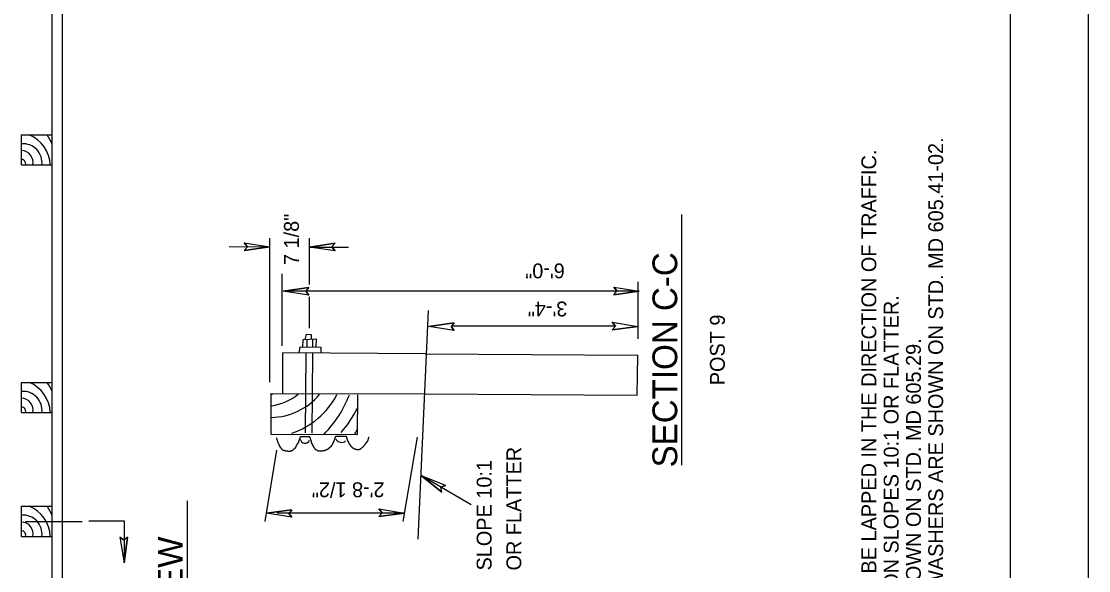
# Model space of a CAD drawing. Extents: x 12.2 to 54.5, y -7.8 to 16.1.
# Drawn here: x 50.224 to 54.534, y -1.531 to 0.687 of the extents above; entities that cross this region are included whole.
import ezdxf

# ---------------------------------------------------------------- set-up
doc = ezdxf.new("R2010")
doc.units = 0
for name, color, linetype in [('BORD-LINE', 7, 'Continuous'), ('DETL-DIMS', 7, 'Continuous'), ('DETL-LINE', 7, 'Continuous'), ('DETL-NOTE', 7, 'Continuous'), ('DETL-PATT', 7, 'Continuous'), ('DETL-TITL', 7, 'Continuous'), ('USER-BORD', 7, 'Continuous')]:
    doc.layers.add(name, color=color, linetype=linetype)

msp = doc.modelspace()

# ---------------------------------------------------------------- linework, layer by layer
at = {"layer": 'BORD-LINE'}
msp.add_lwpolyline([(46.8431, 2.8902), (54.2173, 2.8902), (54.2173, -7.4629), (46.8431, -7.4629)], close=True, dxfattribs=at)
at = {"layer": 'DETL-DIMS'}
for p, q in [((51.1242, -0.2079), (51.2274, -0.2238)), ((51.1242, -0.2079), (51.137, -0.2231)), ((51.2274, -0.7703), (51.2274, -0.1888)), ((51.387, -0.3756), (51.387, -0.1888)), ((51.4911, -0.209), (51.3879, -0.2247)), ((51.4911, -0.209), (51.4783, -0.2242)), ((51.0635, -0.2225), (51.2274, -0.2238)), ((51.1239, -0.238), (51.137, -0.2231)), ((51.1239, -0.238), (51.2274, -0.2238)), ((51.3879, -0.2247), (51.5451, -0.2247)), ((51.4913, -0.2392), (51.3879, -0.2247)), ((51.4913, -0.2392), (51.4783, -0.2242)), ((51.2778, -0.6229), (51.2778, -0.3322)), ((52.6164, -0.3869), (52.7196, -0.4025)), ((52.6164, -0.3869), (52.6292, -0.402)), ((52.7138, -0.3656), (52.7133, -0.5955)), ((51.3852, -0.388), (51.2818, -0.4025)), ((51.385, -0.4182), (51.2818, -0.4025)), ((52.7196, -0.4025), (51.2866, -0.4025)), ((51.3852, -0.388), (51.3721, -0.403)), ((51.385, -0.4182), (51.3721, -0.403)), ((51.387, -0.5521), (51.387, -0.4256)), ((52.6162, -0.417), (52.6292, -0.402)), ((52.6162, -0.417), (52.7196, -0.4025)), ((51.9723, -0.531), (51.8689, -0.5448)), ((51.972, -0.5611), (51.8689, -0.5448)), ((51.9723, -0.531), (51.9592, -0.5459)), ((51.972, -0.5611), (51.9592, -0.5459)), ((52.6232, -0.544), (51.9622, -0.5434)), ((52.6102, -0.5587), (52.6232, -0.5437)), ((52.6102, -0.5587), (52.7137, -0.5448)), ((52.6105, -0.5285), (52.7137, -0.5448)), ((52.6105, -0.5285), (52.6232, -0.5437)), ((51.8221, -0.9925), (51.765, -1.3335)), ((51.2547, -1.045), (51.2076, -1.3336)), ((51.922, -1.214), (51.8403, -1.1489)), ((51.9371, -1.188), (51.8403, -1.1489)), ((52.0409, -1.266), (51.8403, -1.1489)), ((51.9371, -1.188), (51.9184, -1.1945)), ((51.922, -1.214), (51.9184, -1.1945)), ((51.3167, -1.2857), (51.2132, -1.299)), ((51.3167, -1.2857), (51.3035, -1.3005)), ((51.6678, -1.2822), (51.7708, -1.299)), ((51.6678, -1.2822), (51.6805, -1.2975)), ((50.2409, -1.3325), (50.4698, -1.3325)), ((50.497, -1.3297), (50.6386, -1.3297)), ((50.6386, -1.33), (50.6386, -1.4993)), ((51.3162, -1.3158), (51.2132, -1.299)), ((51.7708, -1.299), (51.257, -1.299)), ((51.3162, -1.3158), (51.3035, -1.3005)), ((51.6674, -1.3123), (51.6805, -1.2975)), ((51.6674, -1.3123), (51.7708, -1.299)), ((50.6219, -1.3962), (50.6386, -1.4993)), ((50.6219, -1.3962), (50.6372, -1.4088)), ((50.6521, -1.3957), (50.6372, -1.4088)), ((50.6521, -1.3957), (50.6386, -1.4993))]:
    msp.add_line(p, q, dxfattribs=at)
for points in [[(51.1242, -0.2079), (51.2274, -0.2238), (51.1239, -0.238), (51.137, -0.2231)], [(51.4913, -0.2392), (51.3879, -0.2247), (51.4911, -0.209), (51.4783, -0.2242)], [(52.6164, -0.3869), (52.7196, -0.4025), (52.6162, -0.417), (52.6292, -0.402)], [(51.385, -0.4182), (51.2818, -0.4025), (51.3852, -0.388), (51.3721, -0.403)], [(51.972, -0.5611), (51.8689, -0.5448), (51.9723, -0.531), (51.9592, -0.5459)], [(52.6105, -0.5285), (52.7137, -0.5448), (52.6102, -0.5587), (52.6232, -0.5437)], [(51.9371, -1.188), (51.8403, -1.1489), (51.922, -1.214), (51.9184, -1.1945)], [(51.3162, -1.3158), (51.2132, -1.299), (51.3167, -1.2857), (51.3035, -1.3005)], [(51.6678, -1.2822), (51.7708, -1.299), (51.6674, -1.3123), (51.6805, -1.2975)], [(50.6219, -1.3962), (50.6386, -1.4993), (50.6521, -1.3957), (50.6372, -1.4088)]]:
    msp.add_lwpolyline(points, close=True, dxfattribs=at)
at = {"layer": 'DETL-LINE'}
for p, q in [((50.3485, -5.332), (50.3485, 2.7601)), ((50.3897, -5.332), (50.3897, 2.7851)), ((50.225, 0.1071), (50.225, 0.229)), ((50.225, 0.229), (50.3485, 0.229)), ((50.3485, 0.1071), (50.3485, 0.229)), ((50.3485, 0.168), (50.3485, 0.168)), ((50.3485, 0.168), (50.3485, 0.168)), ((50.225, 0.1071), (50.3485, 0.1071)), ((51.8674, -0.4802), (51.8253, -1.4042)), ((51.3611, -0.6281), (51.362, -0.5978)), ((51.362, -0.5978), (51.4143, -0.5955)), ((51.3706, -0.5974), (51.3757, -0.5767)), ((51.3757, -0.5767), (51.3947, -0.5775)), ((51.3768, -0.5971), (51.3764, -0.6281)), ((51.3947, -0.5775), (51.3948, -0.5964)), ((51.3995, -0.5961), (51.3998, -0.6282)), ((51.4143, -0.5955), (51.413, -0.6283)), ((51.3461, -0.6529), (51.3493, -0.628)), ((51.3493, -0.628), (51.4327, -0.6284)), ((51.4327, -0.6284), (51.4332, -0.6534)), ((51.855, -0.6556), (51.2792, -0.6522)), ((51.2793, -0.8167), (51.2803, -0.6522)), ((51.3719, -0.9755), (51.3745, -0.653)), ((51.3997, -0.6532), (51.3971, -0.9756)), ((51.855, -0.6556), (52.7133, -0.6605)), ((52.7114, -0.8228), (52.7133, -0.6605)), ((50.225, -0.8929), (50.225, -0.771)), ((50.225, -0.771), (50.3485, -0.771)), ((50.3485, -0.8929), (50.3485, -0.771)), ((51.2316, -0.816), (51.231, -0.9804)), ((51.2316, -0.816), (51.8516, -0.818)), ((51.8516, -0.818), (52.7114, -0.8228)), ((50.3485, -0.832), (50.3485, -0.832)), ((51.581, -0.9817), (51.5826, -0.8215)), ((52.7114, -0.8228), (52.7114, -0.8228)), ((50.225, -0.8929), (50.3485, -0.8929)), ((51.231, -0.9804), (51.581, -0.9817)), ((51.3516, -0.9896), (51.3885, -0.9896)), ((51.4935, -0.9877), (51.5366, -0.9877)), ((50.225, -1.3929), (50.225, -1.271)), ((50.225, -1.271), (50.3485, -1.271)), ((50.3485, -1.3929), (50.3485, -1.271)), ((50.3485, -1.332), (50.3485, -1.332)), ((50.225, -1.3929), (50.3485, -1.3929))]:
    msp.add_line(p, q, dxfattribs=at)
for centre, radius, start, end in [((51.3697, -0.997), 0.02, 188.3494, 336.752), ((51.5167, -0.9864), 0.0269, 209.5517, 308.2673)]:
    msp.add_arc(centre, radius, start, end, dxfattribs=at)
for points in [[(51.2535, -0.9932), (51.2555, -0.9989), (51.256, -1.0017), (51.2569, -1.0041), (51.2579, -1.0079), (51.2588, -1.0084), (51.2589, -1.0102), (51.2594, -1.0117), (51.2598, -1.0137), (51.2603, -1.0137), (51.2603, -1.0155), (51.2617, -1.0175), (51.2617, -1.0189), (51.2627, -1.0203), (51.2632, -1.0202), (51.2642, -1.0241), (51.2652, -1.025), (51.2652, -1.0255), (51.2656, -1.027), (51.2665, -1.027), (51.267, -1.0284), (51.2675, -1.0303), (51.2685, -1.0303), (51.2685, -1.0317), (51.2695, -1.0332), (51.27, -1.0337), (51.2705, -1.0345), (51.2713, -1.0345), (51.2713, -1.036), (51.2728, -1.0379), (51.2743, -1.0388), (51.2752, -1.0393), (51.2757, -1.0412), (51.2771, -1.0422), (51.2771, -1.0427), (51.2786, -1.0436), (51.2805, -1.044), (51.2819, -1.0445), (51.2838, -1.045), (51.2843, -1.0454), (51.2857, -1.0459), (51.2886, -1.0459), (51.2896, -1.0469), (51.2914, -1.0469), (51.2953, -1.0478), (51.2986, -1.0478), (51.2996, -1.0483), (51.3001, -1.0483), (51.3014, -1.0486), (51.3029, -1.0483), (51.3043, -1.0486), (51.3062, -1.0486), (51.3091, -1.0486), (51.311, -1.0482), (51.3138, -1.0486), (51.3152, -1.0467), (51.3167, -1.0467), (51.3181, -1.0452), (51.3196, -1.0447), (51.3199, -1.0437), (51.3219, -1.0434), (51.3229, -1.0419), (51.3234, -1.0424), (51.3247, -1.0409), (51.3247, -1.0404), (51.3261, -1.0394), (51.3261, -1.0389), (51.3276, -1.038), (51.3271, -1.0376), (51.329, -1.0366), (51.3314, -1.0341), (51.3313, -1.0328), (51.3328, -1.0328), (51.3338, -1.0303), (51.3351, -1.0255), (51.3366, -1.025), (51.3375, -1.0227), (51.3385, -1.0222), (51.339, -1.0193), (51.3403, -1.0174), (51.3413, -1.0155), (51.3427, -1.0149), (51.3445, -1.0083), (51.3455, -1.0068), (51.346, -1.0064), (51.3464, -1.0054), (51.3474, -1.0021), (51.3488, -0.9988), (51.3488, -0.9968), (51.3497, -0.9948), (51.3507, -0.992), (51.3516, -0.9896), (51.3521, -0.9892)], [(51.3883, -0.9913), (51.3878, -0.9913), (51.3887, -0.9937), (51.3897, -0.9946), (51.3902, -0.998), (51.3907, -0.9998), (51.3912, -1.0018), (51.3922, -1.0046), (51.3932, -1.0046), (51.3932, -1.008), (51.3936, -1.0098), (51.3946, -1.0098), (51.3941, -1.0113), (51.395, -1.0142), (51.396, -1.0146), (51.3961, -1.0175), (51.397, -1.019), (51.398, -1.0194), (51.3984, -1.0218), (51.3989, -1.0233), (51.3999, -1.0237), (51.4004, -1.0246), (51.4004, -1.0261), (51.4019, -1.0275), (51.4019, -1.0289), (51.4028, -1.0303), (51.4047, -1.0333), (51.4057, -1.0351), (51.4066, -1.0356), (51.4071, -1.0365), (51.408, -1.037), (51.4095, -1.0389), (51.4124, -1.0418), (51.4143, -1.0432), (51.4157, -1.0441), (51.4177, -1.0441), (51.419, -1.0455), (51.4248, -1.047), (51.4272, -1.047), (51.4286, -1.0474), (51.4315, -1.0474), (51.4328, -1.0479), (51.4348, -1.0478), (51.4362, -1.0474), (51.441, -1.0473), (51.4424, -1.0468), (51.4438, -1.0468), (51.4467, -1.0458), (51.4481, -1.0458), (51.4486, -1.0453), (51.4495, -1.0453), (51.4538, -1.0438), (51.4553, -1.0438), (51.4567, -1.0429), (51.4571, -1.0425), (51.461, -1.0405), (51.4623, -1.0395), (51.4623, -1.039), (51.4638, -1.039), (51.4657, -1.0371), (51.4671, -1.0356), (51.4685, -1.0347), (51.4685, -1.0338), (51.47, -1.0333), (51.4709, -1.0318), (51.4718, -1.0318), (51.4733, -1.0298), (51.4757, -1.0294), (51.477, -1.026), (51.4784, -1.0237), (51.4799, -1.0237), (51.4799, -1.0222), (51.4804, -1.0207), (51.4814, -1.0207), (51.4813, -1.0193), (51.4817, -1.0179), (51.4827, -1.0164), (51.4837, -1.0145), (51.4842, -1.015), (51.4856, -1.0126), (51.4856, -1.0107), (51.4861, -1.0092), (51.4869, -1.0069), (51.4879, -1.0054), (51.4884, -1.0044), (51.4893, -1.0021), (51.4898, -1.0006), (51.4903, -0.9983), (51.4916, -0.9935), (51.4926, -0.9915), (51.4935, -0.9892), (51.4935, -0.9877)], [(51.5353, -0.9883), (51.5363, -0.9917), (51.5373, -0.9931), (51.5373, -0.9964), (51.5378, -0.9983), (51.5388, -1.0002), (51.5397, -1.0017), (51.5397, -1.0031), (51.5402, -1.0031), (51.5407, -1.0055), (51.5411, -1.0069), (51.5416, -1.0074), (51.5431, -1.0102), (51.5436, -1.0107), (51.5446, -1.0126), (51.5446, -1.0141), (51.5451, -1.0155), (51.5459, -1.0154), (51.5465, -1.0174), (51.5474, -1.0179), (51.5484, -1.0202), (51.5494, -1.0212), (51.5499, -1.0222), (51.5503, -1.0236), (51.5507, -1.0231), (51.5522, -1.0249), (51.5532, -1.0264), (51.5537, -1.0274), (51.5546, -1.0279), (51.555, -1.0288), (51.5565, -1.0292), (51.5565, -1.0307), (51.558, -1.0321), (51.5599, -1.0336), (51.5613, -1.0349), (51.5628, -1.0359), (51.5638, -1.0364), (51.5642, -1.0369), (51.5656, -1.0369), (51.5661, -1.0378), (51.567, -1.0383), (51.5685, -1.0392), (51.5704, -1.0397), (51.5718, -1.0401), (51.5723, -1.0406), (51.5733, -1.0406), (51.579, -1.0425), (51.5846, -1.0425), (51.5881, -1.042), (51.5894, -1.041), (51.5908, -1.041), (51.5942, -1.0395), (51.5956, -1.0376), (51.5971, -1.0366), (51.5985, -1.0361), (51.6023, -1.0323), (51.6046, -1.0318), (51.606, -1.0285), (51.6089, -1.026), (51.6098, -1.0246), (51.6103, -1.0241), (51.6113, -1.0227), (51.6127, -1.0212), (51.6155, -1.0169), (51.6165, -1.0164), (51.6169, -1.015), (51.6179, -1.0131), (51.6198, -1.0121), (51.6202, -1.0107), (51.6212, -1.0092), (51.6222, -1.0068), (51.6235, -1.0059), (51.624, -1.0044), (51.624, -1.003), (51.6254, -0.9992), (51.6254, -0.9973), (51.6268, -0.9953), (51.6278, -0.993), (51.6283, -0.9925)]]:
    msp.add_spline(points, degree=3, dxfattribs=at)
at = {"layer": 'DETL-PATT'}
for centre, radius, start, end in [((51.1662, -0.5902), 0.2391, 286.6952, 287.6506), ((51.1894, -0.6162), 0.2538, 280.0268, 306.912), ((51.2281, -0.6512), 0.2617, 271.1987, 319.858), ((51.2151, -0.6728), 0.3197, 288.3721, 332.445), ((51.1228, -0.6589), 0.4557, 315.2141, 339.1469), ((51.097, -0.6241), 0.5456, 320.1581, 332.7687), ((50.6543, -0.4058), 1.0804, 327.9748, 329.0858)]:
    msp.add_arc(centre, radius, start, end, dxfattribs=at)
for centre, major_axis, start_param, end_param in [((50.205, 0.1017), (0, 0.137), 4.750897, 5.899278), ((50.0724, 0.0628), (0, 0.3071), 5.144981, 5.283467), ((50.2309, 0.1156), (0, 0.0772), 4.600695, 6.361038), ((50.2243, 0.1121), (0, 0.0174), 4.485117, 6.270221), ((50.2243, 0.1177), (0, 0.0472), 4.485117, 6.270221), ((50.205, -0.8983), (0, 0.137), 4.750897, 5.899278), ((50.0724, -0.9372), (0, 0.3071), 5.144981, 5.283467), ((50.2309, -0.8844), (0, 0.0772), 4.600695, 6.361038), ((50.2243, -0.8823), (0, 0.0472), 4.485117, 6.270221), ((50.2243, -0.8879), (0, 0.0174), 4.485117, 6.270221), ((50.205, -1.3983), (0, 0.137), 4.750897, 5.899278), ((50.0724, -1.4372), (0, 0.3071), 5.144981, 5.283467), ((50.2309, -1.3844), (0, 0.0772), 4.600695, 6.361038), ((50.2243, -1.3823), (0, 0.0472), 4.485117, 6.270221), ((50.2243, -1.3879), (0, 0.0174), 4.485117, 6.270221)]:
    msp.add_ellipse(centre, major_axis=major_axis, ratio=0.989796, start_param=start_param, end_param=end_param, dxfattribs=at)
at = {"layer": 'DETL-TITL'}
for p, q in [((52.8911, -1.106), (52.8911, -0.0926)), ((50.8942, -2.121), (50.8942, -1.25))]:
    msp.add_line(p, q, dxfattribs=at)
at = {"layer": 'USER-BORD'}
msp.add_lwpolyline([(54.5342, 3.2202), (46.0342, 3.2202), (46.0342, -7.7798), (54.5342, -7.7798)], close=True, dxfattribs=at)

# ---------------------------------------------------------------- texts
at = {"layer": 'DETL-NOTE'}
for s, rotation, p in [('5. DETAILS OF THE TERMINAL CONNECTOR, TRANSITION SECTION, AND RECTANGULAR PLATE WASHERS ARE SHOWN ON STD. MD 605.41-02.', 90, (53.9466, -5.3634)), ('2. THRIE-BEAM TERMINAL CONNECTOR, THRIE-BEAM SECTIONS, AND W-BEAM SECTIONS SHALL BE LAPPED IN THE DIRECTION OF TRAFFIC.', 90, (53.6766, -5.3634)), ('7 1/8"', 90, (51.3445, -0.297)), ('6\'-0"', 180, (52.4186, -0.2907)), ('3. THE TRAFFIC BARRIER THRIE-BEAM ANCHORAGE AT BRIDGE END POSTS SHALL BE PLACED ON SLOPES 10:1 OR FLATTER.', 90, (53.7666, -5.3634)), ('3\'-4"', 180, (52.429, -0.4447)), ('POST 9', 90, (53.0649, -0.7826)), ('4. DETAILS OF THE DOUBLE (NESTED) THRIE-BEAM, WOOD OFFSET BLOCK, AND SPLICE ARE SHOWN ON STD. MD 605.29.', 90, (53.8566, -5.3634)), ('OR FLATTER', 90, (52.2428, -1.5307)), ('SLOPE 10:1', 90, (52.1228, -1.5307)), ('2\'-8 1/2"', 180, (51.6906, -1.1748))]:
    msp.add_text(s, height=0.06, rotation=rotation, dxfattribs=at).set_placement(p)
at = {"layer": 'DETL-TITL'}
for s, p in [('SECTION C-C', (52.8726, -1.1146)), ('PLAN VIEW', (50.8757, -2.122))]:
    msp.add_text(s, height=0.1, rotation=90, dxfattribs=at).set_placement(p)

doc.saveas('drawing.dxf')
